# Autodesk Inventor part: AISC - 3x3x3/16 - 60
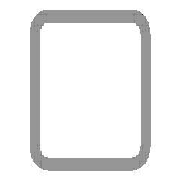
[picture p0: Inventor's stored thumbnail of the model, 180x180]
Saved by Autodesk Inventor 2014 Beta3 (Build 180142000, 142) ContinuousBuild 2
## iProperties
_CCFamilyMember: 9
_CCFamilyDisplayName: ANSI AISC (Square) - Tube
_FrameMemberDoc: Frame Member File
_Version: 15.0.0
_GetPNFromCC: 1
Created: 2011-01
Part Number: AISC - 3x3x3/16 - 60
Material: Steel, Mild
Description: Tube
Document SubType Name: Modeling
Standard: ANSI
Designer: Beta-8540w
Standards Organization: ANSI
Language: en-US
Size Designation: 3x3x3/16
Categories: <MemberInstance><Categories><Category DisplayName="Structural Shapes" InternalName="089c4875-fa83-4c05-b084-43b9cc11f5ed" Mnemonic="GRDR"><CategoryParameter Dis
Stock Number: 3x3x3/16
Density: 7.86 g/cm^3
Appearance: Steel
IsCustomPart: 1
G_L: 60.000 in
G_W: 3.000 in
G_H: 3.000 in
Author: Beta-8540w
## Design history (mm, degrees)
node "Start plane"
node "End plane"
sketch "Sketch"
  geometry: L1 (-38.1, -28.575)-(-38.1, 28.575); L2 (-28.575, 38.1)-(28.575, 38.1); L3 (38.1, 28.575)-(38.1, -28.575); L4 (28.575, -38.1)-(-28.575, -38.1); L5 (-28.575, 33.337)-(28.575, 33.338); L6 (33.338, 28.575)-(33.338, -28.575); L7 (28.575, -33.337)-(-28.575, -33.338); L8 (-33.338, -28.575)-(-33.338, 28.575); L9 (0, 56.102)-(0, -56.102) reference; L10 (-56.102, 0)-(56.102, 0) reference; A1 r 9.525 centre (-28.575, -28.575) between (-38.1, -28.575) and (-28.575, -38.1); A2 r 9.525 centre (-28.575, 28.575) between (-28.575, 38.1) and (-38.1, 28.575); A3 r 9.525 centre (28.575, 28.575) between (38.1, 28.575) and (28.575, 38.1); A4 r 9.525 centre (28.575, -28.575) between (28.575, -38.1) and (38.1, -28.575); A5 r 4.763 centre (-28.575, 28.575) between (-28.575, 33.337) and (-33.338, 28.575); A6 r 4.763 centre (28.575, 28.575) between (33.338, 28.575) and (28.575, 33.338); A7 r 4.763 centre (28.575, -28.575) between (28.575, -33.337) and (33.338, -28.575); A8 r 4.763 centre (-28.575, -28.575) between (-33.338, -28.575) and (-28.575, -33.338)
  constraints: 16 end point, 16 point on circle, 8 centre point, 8 tangent, 4 parallel, 3 equal radius, 2 perpendicular, 7 other
  dimensions: "d10" = 76.2 distance between parallel lines of L2 L4 (= G_H); "d11" = 76.2 distance between parallel lines of L1 L3 (= G_W); "d12" = 4.7625 distance between parallel lines of L3 L6 (= G_T); "d15" = 38.1 distance between parallel lines of L2 L10 (= 0.5 x d10); "d16" = 38.1 distance between parallel lines of L9 L3 (= 0.5 x d11); "d17" = 9.525 radius of A1 (= G_IR)
extrude "Body" new body sketch "Sketch" stored distance "d3" = 1524 (= G_L); taper "d4" = 0 deg
node "Driven Length"
  sketch "Sketch3"
    geometry: L1 (0, 0)-(10, 0) reference
    constraints: 2 end point, 1 horizontal
  workplane "Work Plane3"
  sketch "Sketch4"
    geometry: L1 (-2, 0)-(12, 0) reference; L2 (-2, 1524)-(12, 1524) reference
    dimensions: "d19" = 1524 distance between parallel lines of L1 L2 (derived)
body "Solid1"
other parameters: "G_W" = 76.2 [user parameter; used in 1 equation term], "G_H" = 76.2 [user parameter; used in 1 equation term], "G_T" = 4.7625 [user parameter; used in 1 equation term], "G_IR" = 9.525 [user parameter; used in 1 equation term], "G_L" = 1524 (= d19) [user parameter; used in 1 equation term], "G_OFFSET_START" = 0 [user parameter; used in 1 equation term], "G_OFFSET_END" = 0 [user parameter; used in 1 equation term], "d13" = 0 (computed from G_OFFSET_START), "d14" = 1524 (= G_OFFSET_END + B_L), "B_L" = 1524 [user parameter; used in 1 equation term], "d18" = 90 deg
